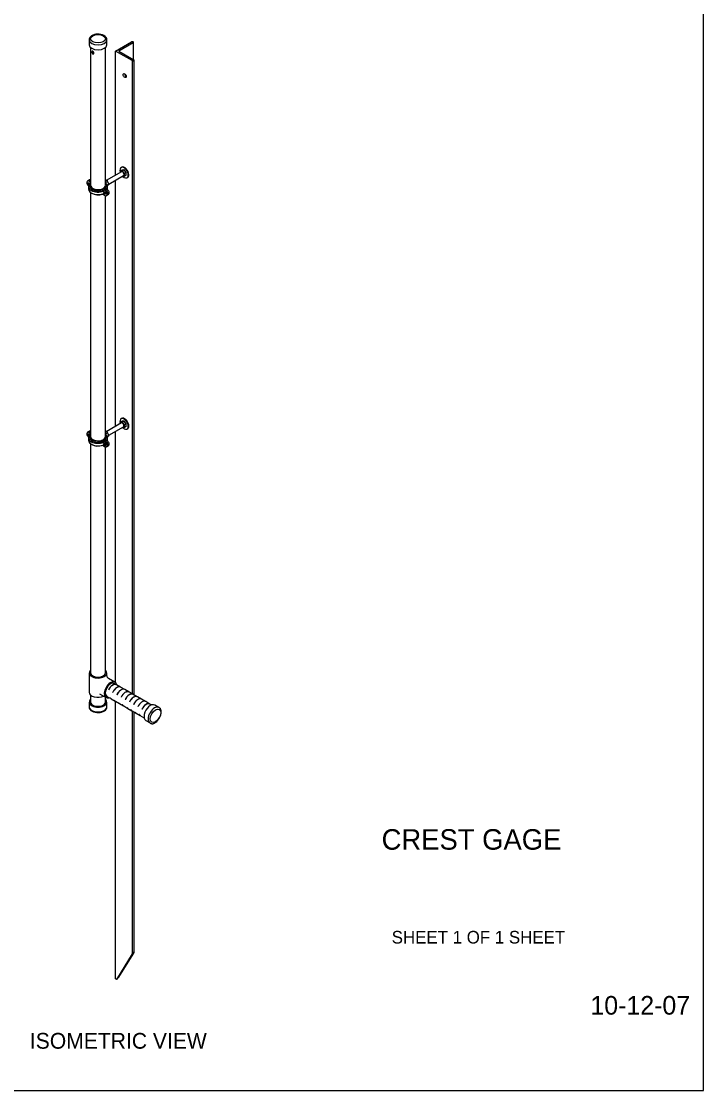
# Model space of a CAD drawing. Extents: x 99862 to 103151, y 100000 to 102076.
# Drawn here: x 102286 to 103151, y 100000 to 101354 of the extents above; entities that cross this region are included whole.
import ezdxf

# ---------------------------------------------------------------- set-up
doc = ezdxf.new("R2010")
doc.units = 0
for name, color, linetype in [('Level 1', 7, 'Continuous'), ('Level 10', 7, 'Continuous'), ('Level 13', 7, 'Continuous'), ('Level 15', 7, 'Continuous'), ('Level 20', 7, 'Continuous'), ('Level 27', 7, 'Continuous'), ('Level 3', 7, 'Continuous'), ('Level 4', 7, 'Continuous'), ('Level 5', 7, 'Continuous'), ('Level 62', 7, 'Continuous'), ('Level 7', 7, 'Continuous'), ('Level 8', 7, 'Continuous')]:
    doc.layers.add(name, color=color, linetype=linetype)

msp = doc.modelspace()

# ---------------------------------------------------------------- linework, layer by layer
at = {"layer": 'Level 1'}
msp.add_lwpolyline([(99862, 99999.5), (103151, 99999.5), (103151, 102075.5), (99862, 102075.5)], close=True, dxfattribs=at)
at = {"layer": 'Level 10'}
for p, q in [((102406.1, 100513.9), (102403.5, 100515.5)), ((102411.4, 100510.9), (102406.3, 100513.9)), ((102416.8, 100507.8), (102411.6, 100510.8)), ((102394.3, 100499.1), (102399.4, 100496.2)), ((102396.4, 100507.5), (102396.2, 100507.3)), ((102396.3, 100507.3), (102396.2, 100507.3)), ((102401.7, 100504.4), (102401.5, 100504.3)), ((102401.6, 100504.2), (102401.5, 100504.3)), ((102407, 100501.4), (102406.8, 100501.2)), ((102406.9, 100501.1), (102406.8, 100501.2)), ((102412.3, 100498.3), (102412.1, 100498.2)), ((102412.2, 100498.1), (102412.1, 100498.2)), ((102422.1, 100504.7), (102416.9, 100507.7)), ((102427.4, 100501.7), (102422.2, 100504.7)), ((102432.7, 100498.6), (102427.5, 100501.6)), ((102438, 100495.6), (102432.8, 100498.5)), ((102399.6, 100496.1), (102404.7, 100493.1)), ((102404.9, 100493), (102410, 100490)), ((102410.2, 100490), (102415.3, 100487)), ((102415.5, 100486.9), (102420.6, 100483.9)), ((102417.6, 100495.2), (102417.4, 100495.1)), ((102417.5, 100495), (102417.4, 100495.1)), ((102420.8, 100483.8), (102425.9, 100480.8)), ((102422.9, 100492.2), (102422.7, 100492)), ((102422.8, 100492), (102422.7, 100492)), ((102428.2, 100489.1), (102428, 100489)), ((102428.1, 100488.9), (102428, 100489)), ((102433.5, 100486), (102433.3, 100485.9)), ((102433.4, 100485.8), (102433.3, 100485.9)), ((102443.3, 100492.5), (102438.1, 100495.5)), ((102448.6, 100489.4), (102443.4, 100492.4)), ((102450.8, 100488.2), (102448.7, 100489.4)), ((102426.1, 100480.8), (102431.2, 100477.8)), ((102431.4, 100477.7), (102436.5, 100474.7)), ((102436.7, 100474.6), (102441.4, 100471.9)), ((102438.8, 100483), (102438.6, 100482.8)), ((102438.7, 100482.8), (102438.6, 100482.8))]:
    msp.add_line(p, q, dxfattribs=at)
for centre, major_axis, start_param, end_param in [((102401.5, 100505.8), (4.69, 8.12), 6.269043, 7.995879), ((102401.6, 100505.7), (-4.69, -8.12), 3.141562, 4.854286), ((102406.8, 100502.7), (4.69, 8.12), 6.269043, 7.995879), ((102406.9, 100502.7), (-4.69, -8.12), 3.141593, 4.854286), ((102398.9, 100507.3), (-4.69, -8.12), 6.269043, 6.283192), ((102404.1, 100504.3), (4.69, 8.12), 2.824492, 3.155735), ((102404.2, 100504.2), (-4.69, -8.12), 5.966084, 6.283185), ((102412.1, 100499.7), (4.69, 8.12), 6.269043, 7.995879), ((102412.2, 100499.6), (-4.69, -8.12), 3.141564, 4.854286), ((102417.4, 100496.6), (4.69, 8.12), 6.269043, 7.995879), ((102417.5, 100496.5), (-4.69, -8.12), 3.141555, 4.854286), ((102422.7, 100493.6), (4.69, 8.12), 6.269043, 7.995879), ((102422.8, 100493.5), (-4.69, -8.12), 3.141567, 4.854286), ((102428, 100490.5), (4.69, 8.12), 6.269043, 7.995879), ((102428.1, 100490.4), (-4.69, -8.12), 3.141593, 4.854286), ((102409.4, 100501.2), (4.69, 8.12), 2.824492, 3.155735), ((102409.5, 100501.1), (-4.69, -8.12), 5.966084, 6.283185), ((102414.7, 100498.2), (4.69, 8.12), 2.824492, 3.155735), ((102414.8, 100498.1), (-4.69, -8.12), 5.966084, 6.283185), ((102420, 100495.1), (4.69, 8.12), 2.824492, 3.155735), ((102420.2, 100495), (-4.69, -8.12), 5.966084, 6.283203), ((102425.3, 100492), (4.69, 8.12), 2.824492, 3.155735), ((102425.5, 100492), (-4.69, -8.12), 5.966084, 6.283185), ((102433.3, 100487.4), (4.69, 8.12), 6.269043, 7.995879), ((102433.4, 100487.4), (-4.69, -8.12), 3.141562, 4.854286), ((102438.6, 100484.4), (4.69, 8.12), 6.269043, 7.995879), ((102438.7, 100484.3), (-4.69, -8.12), 3.141559, 4.854286), ((102443.9, 100481.3), (4.69, 8.12), 6.269043, 7.995879), ((102444, 100481.2), (-4.69, -8.12), 3.141565, 4.854286), ((102430.6, 100489), (4.69, 8.12), 2.824492, 3.155735), ((102430.8, 100488.9), (-4.69, -8.12), 5.966084, 6.283185), ((102435.9, 100485.9), (4.69, 8.12), 2.824492, 3.155735), ((102436.1, 100485.8), (-4.69, -8.12), 5.966084, 6.283185), ((102441.2, 100482.8), (4.69, 8.12), 2.824492, 3.155735), ((102441.4, 100482.8), (-4.69, -8.12), 5.966084, 6.283185), ((102446.5, 100479.8), (4.69, 8.12), 2.824492, 3.035327), ((102446.7, 100479.7), (4.69, 8.12), 2.824492, 3.000447), ((102446.7, 100479.7), (-4.69, -8.12), 6.141288, 6.14204)]:
    msp.add_ellipse(centre, major_axis=major_axis, ratio=0.57735, start_param=start_param, end_param=end_param, dxfattribs=at)
for points in [[(102398.3, 100497.3), (102398.3, 100497.4), (102398.2, 100497.4), (102398.2, 100497.4)], [(102403.6, 100494.3), (102403.6, 100494.3), (102403.5, 100494.3), (102403.5, 100494.3)], [(102408.9, 100491.2), (102408.9, 100491.2), (102408.8, 100491.3), (102408.8, 100491.3)], [(102414.2, 100488.1), (102414.2, 100488.2), (102414.1, 100488.2), (102414.1, 100488.2)], [(102419.5, 100485.1), (102419.5, 100485.1), (102419.5, 100485.1), (102419.4, 100485.2)], [(102424.8, 100482), (102424.8, 100482), (102424.8, 100482.1), (102424.7, 100482.1)], [(102430.1, 100479), (102430.1, 100479), (102430.1, 100479), (102430, 100479)], [(102435.5, 100475.9), (102435.4, 100475.9), (102435.4, 100475.9), (102435.3, 100476)], [(102440.8, 100472.8), (102440.7, 100472.9), (102440.7, 100472.9), (102440.6, 100472.9)]]:
    msp.add_open_spline(points, degree=2, dxfattribs=at)
at = {"layer": 'Level 13'}
for p, q in [((102370.7, 101152.8), (102369.4, 101152.1)), ((102370.4, 101150), (102371.3, 101150)), ((102372.1, 101153.6), (102370.7, 101152.8)), ((102373.5, 101150.6), (102371.3, 101151.9)), ((102371.3, 101150), (102372.2, 101149)), ((102372.2, 101149), (102372.2, 101148.6)), ((102373.5, 101152.1), (102372.6, 101152.7)), ((102373, 101149.4), (102373.4, 101149.1)), ((102395, 101152), (102392.3, 101153.6)), ((102392.3, 101150.4), (102395, 101152)), ((102393.5, 101148.7), (102392.8, 101148.3)), ((102394.7, 101147), (102396.5, 101148)), ((102396.5, 101148), (102395, 101152)), ((102395, 101145.9), (102396.5, 101148)), ((102370.7, 101145.2), (102370.7, 101142.1)), ((102372.6, 101146.7), (102372.6, 101145.2)), ((102388.7, 101141.8), (102388.7, 101140.3)), ((102391.7, 101140.1), (102388.7, 101141.8)), ((102390.1, 101139.5), (102388.7, 101140.3)), ((102388.7, 101136), (102388.7, 101135.7)), ((102388.7, 101135.7), (102391.7, 101134)), ((102393.1, 101140.8), (102389.5, 101142.9)), ((102390.1, 101139.5), (102390.1, 101136.5)), ((102390.8, 101138.2), (102391.7, 101138.2)), ((102394.4, 101141.6), (102391.4, 101143.4)), ((102391.7, 101138.2), (102392.6, 101137.2)), ((102392.6, 101137.2), (102392.6, 101136.5)), ((102392.6, 101136.5), (102392.6, 101135.9)), ((102393.2, 101145.2), (102393.2, 101146.7)), ((102393.6, 101133.8), (102394.9, 101134.5)), ((102394.9, 101134.5), (102396.3, 101135.3)), ((102395, 101145.9), (102395, 101145.9)), ((102395.1, 101142.1), (102395.1, 101145.2)), ((102370.8, 100834.4), (102369.4, 100833.7)), ((102370.4, 100831.6), (102371.3, 100831.6)), ((102370.7, 100826.8), (102370.7, 100823.7)), ((102372.1, 100835.2), (102370.8, 100834.4)), ((102373.5, 100832.2), (102371.3, 100833.5)), ((102371.3, 100831.6), (102372.2, 100830.6)), ((102372.2, 100830.6), (102372.2, 100830.2)), ((102373.5, 100833.7), (102372.6, 100834.2)), ((102372.6, 100828.3), (102372.6, 100826.8)), ((102373.1, 100830.9), (102373.4, 100830.7)), ((102388.7, 100823.4), (102388.7, 100821.9)), ((102391.8, 100821.7), (102388.7, 100823.4)), ((102393.1, 100822.4), (102389.5, 100824.5)), ((102394.4, 100823.2), (102391.4, 100824.9)), ((102395, 100833.6), (102392.3, 100835.2)), ((102392.3, 100832), (102395, 100833.6)), ((102393.5, 100830.3), (102392.8, 100829.9)), ((102393.2, 100826.8), (102393.2, 100828.3)), ((102394.7, 100828.5), (102396.6, 100829.6)), ((102396.6, 100829.6), (102395, 100833.6)), ((102395, 100827.4), (102396.6, 100829.6)), ((102395, 100827.4), (102395, 100827.4)), ((102395.1, 100823.7), (102395.1, 100826.8)), ((102390.1, 100821.1), (102388.7, 100821.9)), ((102388.7, 100817.6), (102388.7, 100817.3)), ((102388.7, 100817.3), (102391.8, 100815.5)), ((102390.1, 100821.1), (102390.1, 100818)), ((102390.8, 100819.8), (102391.8, 100819.8)), ((102391.8, 100819.8), (102392.7, 100818.8)), ((102392.7, 100818.8), (102392.7, 100818.1)), ((102392.7, 100818.1), (102392.7, 100817.5)), ((102393.6, 100815.4), (102395, 100816.1)), ((102395, 100816.1), (102396.3, 100816.9))]:
    msp.add_line(p, q, dxfattribs=at)
for centre, major_axis, start_param, end_param in [((102371.3, 101148.8), (1.87, -3.25), 2.356194, 5.30587), ((102382.9, 101145.2), (-12.2, 0), 5.652247, 8.48492), ((102372.6, 101149.6), (1.87, -3.25), 2.356194, 3.14164), ((102382.9, 101146.7), (10.3, 0), 2.705832, 5.314952), ((102373.9, 101150.4), (1.87, -3.25), 2.515652, 3.141596), ((102382.9, 101146.7), (10.3, 0), 5.680622, 6.706742), ((102382.9, 101145.2), (-12.2, 0), 2.668961, 3.657263), ((102382.9, 101142.1), (-12.2, 0), 6.283185, 8.48492), ((102382.9, 101145.2), (10.3, 0), 3.141591, 5.314952), ((102382.9, 101146.7), (9.37, 0), 3.066795, 6.282088), ((102382.9, 101140.6), (10.3, 0), 3.839772, 5.314952), ((102391.7, 101137), (1.87, -3.25), 5.497787, 8.63938), ((102382.9, 101145.2), (10.3, 0), 5.869956, 6.283185), ((102393.1, 101137.8), (1.87, -3.25), 6.283185, 8.63938), ((102394.4, 101138.6), (1.87, -3.25), 0, 2.356194), ((102382.9, 101142.1), (-12.2, 0), 3.010441, 3.141593), ((102371.3, 100830.4), (1.87, -3.25), 2.356194, 5.30587), ((102382.9, 100826.8), (-12.2, 0), 5.652247, 8.48492), ((102382.9, 100823.7), (-12.2, 0), 6.283185, 8.48492), ((102372.6, 100831.2), (1.87, -3.25), 2.356194, 3.141593), ((102382.9, 100828.3), (10.3, 0), 2.710769, 5.314952), ((102374, 100831.9), (1.87, -3.25), 2.523823, 3.141593), ((102382.9, 100826.8), (10.3, 0), 3.141593, 5.314952), ((102382.9, 100828.3), (9.37, 0), 3.10947, 3.29473), ((102382.9, 100828.3), (10.3, 0), 5.680622, 6.711758), ((102382.9, 100826.8), (10.3, 0), 5.869956, 6.283185), ((102393.1, 100819.4), (1.87, -3.25), 6.283151, 8.63938), ((102382.9, 100826.8), (-12.2, 0), 2.668961, 3.657263), ((102394.4, 100820.1), (1.87, -3.25), 0, 2.356194), ((102382.9, 100823.7), (-12.2, 0), 3.010441, 3.141593), ((102382.9, 100822.2), (10.3, 0), 3.839772, 5.314952), ((102391.8, 100818.6), (1.87, -3.25), 5.497787, 8.63938)]:
    msp.add_ellipse(centre, major_axis=major_axis, ratio=0.57735, start_param=start_param, end_param=end_param, dxfattribs=at)
at = {"layer": 'Level 27'}
for p, q in [((102426.2, 101304.7), (102426.2, 100502.4)), ((102426.2, 100480.7), (102426.2, 100172.7))]:
    msp.add_line(p, q, dxfattribs=at)
at = {"layer": 'Level 3'}
for p, q in [((102373.5, 101321.3), (102373.5, 101146.3)), ((102392.3, 101146.7), (102392.3, 101321.3)), ((102412.5, 101164), (102393.3, 101153)), ((102412.3, 101169.3), (102412.9, 101169.7)), ((102369.7, 101149.6), (102370.4, 101150)), ((102370.6, 101149.6), (102371.3, 101150)), ((102371.5, 101148.6), (102372.2, 101149)), ((102396.5, 101148.3), (102415.3, 101159.1)), ((102419.8, 101156.3), (102420.4, 101156.7)), ((102373.5, 101137.6), (102373.5, 100828.1)), ((102390.2, 101137.8), (102390.8, 101138.2)), ((102391.1, 101137.8), (102391.7, 101138.2)), ((102392.6, 101137.2), (102392, 101136.8)), ((102392, 101135.5), (102392.6, 101135.9)), ((102392.3, 100828.3), (102392.3, 101133.7)), ((102412.3, 100850.9), (102412.9, 100851.3)), ((102412.5, 100845.6), (102393.3, 100834.5)), ((102396.5, 100829.9), (102415.3, 100840.7)), ((102419.8, 100837.9), (102420.4, 100838.3)), ((102369.7, 100831.2), (102370.4, 100831.6)), ((102370.7, 100831.2), (102371.3, 100831.6)), ((102371.5, 100830.2), (102372.2, 100830.6)), ((102373.5, 100819.2), (102373.5, 100528.8)), ((102390.8, 100819.8), (102390.2, 100819.4)), ((102391.8, 100819.8), (102391.1, 100819.4)), ((102392.7, 100818.8), (102392, 100818.4)), ((102392, 100817.1), (102392.7, 100817.5)), ((102392.3, 100528.8), (102392.3, 100815.3)), ((102373.5, 100500.7), (102373.5, 100491.9)), ((102392.3, 100491.9), (102392.3, 100498.1))]:
    msp.add_line(p, q, dxfattribs=at)
for points in [[(102369.7, 101149.6), (102370.6, 101149.6), (102371.5, 101148.6), (102371.5, 101147.9), (102371.5, 101147.8)], [(102371.2, 101147.3), (102370.6, 101147.3), (102369.7, 101148.3), (102369.7, 101149), (102369.7, 101149.6)], [(102369.7, 100831.2), (102370.7, 100831.2), (102371.5, 100830.2), (102371.5, 100829.5), (102371.5, 100829.4)], [(102371.3, 100828.9), (102370.7, 100828.8), (102369.7, 100829.9), (102369.7, 100830.6), (102369.7, 100831.2)]]:
    msp.add_lwpolyline(points, dxfattribs=at)
for points in [[(102390.2, 101137.8), (102391.1, 101137.8), (102392, 101136.8), (102392, 101136.1), (102392, 101135.5), (102391.1, 101135.5), (102390.2, 101136.5), (102390.2, 101137.2)], [(102390.2, 100819.4), (102391.1, 100819.4), (102392, 100818.4), (102392, 100817.7), (102392, 100817.1), (102391.1, 100817), (102390.2, 100818.1), (102390.2, 100818.7)]]:
    msp.add_lwpolyline(points, close=True, dxfattribs=at)
for centre, major_axis, start_param, end_param in [((102416, 101162.8), (3.75, -6.5), 3.053089, 4.328234), ((102416, 101162.8), (3.75, -6.5), 5.157156, 9.336274), ((102416.7, 101163.2), (3.75, -6.5), 0.785398, 3.141593), ((102416.7, 101163.2), (3.75, -6.5), 6.283159, 7.068583), ((102416, 100844.4), (3.75, -6.5), 3.053089, 4.328234), ((102416, 100844.4), (3.75, -6.5), 5.157156, 9.336274), ((102416.7, 100844.8), (3.75, -6.5), 6.283185, 9.42482), ((102382.9, 100828.3), (-9.37, 0), 0.149717, 3.141593)]:
    msp.add_ellipse(centre, major_axis=major_axis, ratio=0.57735, start_param=start_param, end_param=end_param, dxfattribs=at)
for points in [[(102376.3, 101316.4), (102376.4, 101316.4), (102376.6, 101316.2), (102376.7, 101316.1), (102376.9, 101316), (102377, 101315.8), (102377.1, 101315.7), (102377.3, 101315.5), (102377.4, 101315.3), (102377.5, 101315.1), (102377.6, 101315), (102377.6, 101314.8), (102377.7, 101314.6), (102377.7, 101314.4), (102377.7, 101314.2), (102377.7, 101314.1), (102377.7, 101313.9), (102377.7, 101313.8), (102377.6, 101313.6), (102377.5, 101313.5), (102377.4, 101313.4), (102377.3, 101313.3), (102377.2, 101313.3), (102377, 101313.2), (102376.9, 101313.2), (102376.7, 101313.2), (102376.6, 101313.2), (102376.4, 101313.3), (102376.3, 101313.4), (102376.1, 101313.4), (102376, 101313.6), (102375.9, 101313.7), (102375.7, 101313.8), (102375.6, 101314), (102375.5, 101314.2), (102375.4, 101314.4), (102375.3, 101314.6), (102375.2, 101314.8), (102375.2, 101315), (102375.1, 101315.2), (102375.1, 101315.3), (102375.1, 101315.5), (102375.1, 101315.7), (102375.1, 101315.9), (102375.1, 101316), (102375.1, 101316.2), (102375.2, 101316.3), (102375.2, 101316.4), (102375.3, 101316.5), (102375.4, 101316.6), (102375.5, 101316.6), (102375.6, 101316.6), (102375.7, 101316.6), (102375.8, 101316.6), (102375.9, 101316.6), (102376, 101316.6), (102376.2, 101316.5), (102376.3, 101316.4)], [(102376.4, 101316.3), (102376.5, 101316.2), (102376.5, 101316), (102376.5, 101315.8), (102376.6, 101315.6), (102376.6, 101315.4), (102376.7, 101315.2), (102376.8, 101315), (102376.9, 101314.8), (102377, 101314.7), (102377.1, 101314.5), (102377.3, 101314.4), (102377.4, 101314.3), (102377.5, 101314.2), (102377.6, 101314.1), (102377.7, 101314.1)]]:
    msp.add_open_spline(points, degree=3, dxfattribs=at)
at = {"layer": 'Level 4'}
for p, q in [((102371.6, 100528.8), (102371.6, 100504.3)), ((102394.1, 100525.2), (102394.1, 100528.8)), ((102404.4, 100517.1), (102396, 100521.9)), ((102403.5, 100515.5), (102403.5, 100515.5)), ((102384.8, 100502.5), (102393.2, 100497.6))]:
    msp.add_line(p, q, dxfattribs=at)
msp.add_arc((102397.9, 100525.2), 3.75, 180, 240, dxfattribs=at)
for centre, major_axis, start_param, end_param in [((102382.9, 100528.8), (11.2, 0), 2.555907, 5.497787), ((102382.9, 100528.8), (9.37, 0), 3.141593, 6.283146), ((102382.9, 100528.8), (11.2, 0), 5.497787, 6.868871), ((102382.9, 100528.8), (9.37, 0), 6.283146, 6.283225), ((102398.8, 100507.3), (5.62, 9.74), 5.6975, 10.010464), ((102398.8, 100507.3), (-4.69, -8.12), 3.14156, 6.297328), ((102382.9, 100504.3), (11.2, 0), 3.141593, 5.416818)]:
    msp.add_ellipse(centre, major_axis=major_axis, ratio=0.57735, start_param=start_param, end_param=end_param, dxfattribs=at)
at = {"layer": 'Level 5'}
for p, q in [((102371.6, 101331), (102371.6, 101324.9)), ((102394.1, 101324.9), (102394.1, 101331)), ((102371.6, 100491.9), (102371.6, 100485.8)), ((102394.1, 100485.8), (102394.1, 100491.9)), ((102460.1, 100484.9), (102454.8, 100488)), ((102443.6, 100468.5), (102448.9, 100465.4))]:
    msp.add_line(p, q, dxfattribs=at)
for centre, major_axis in [((102382.9, 101332.5), (9.37, 0)), ((102455.8, 100474.4), (-4.69, -8.12))]:
    msp.add_ellipse(centre, major_axis=major_axis, ratio=0.57735, dxfattribs=at)
for centre, major_axis, start_param, end_param in [((102382.9, 101331), (11.2, 0), 3.141593, 6.283185), ((102382.9, 101324.9), (11.2, 0), 3.141593, 6.283185), ((102382.9, 100491.9), (-11.2, 0), 5.6975, 10.010464), ((102382.9, 100485.8), (-11.2, 0), 0, 3.141593), ((102382.9, 100491.9), (-9.37, 0), 6.283137, 9.424778), ((102449.2, 100478.3), (-5.62, -9.74), 3.141562, 6.283185), ((102454.5, 100475.2), (-5.62, -9.74), 3.141593, 6.283185)]:
    msp.add_ellipse(centre, major_axis=major_axis, ratio=0.57735, start_param=start_param, end_param=end_param, dxfattribs=at)
for points, degree in [([(102394.1, 101331), (102394.2, 101333.3), (102391.2, 101337.1), (102382.3, 101339), (102374.1, 101336.7), (102371.6, 101333), (102371.6, 101331)], 3), ([(102371.6, 100485.8), (102371.6, 100483.5), (102374.6, 100479.7), (102383.5, 100477.8), (102391.7, 100480.1), (102394.2, 100483.8), (102394.1, 100485.8)], 3), ([(102455.4, 100465.9), (102458.1, 100467.5), (102463.8, 100474.7), (102463.4, 100483.1), (102460.1, 100484.9)], 3), ([(102448.9, 100465.4), (102450.8, 100464.3), (102453.3, 100464.6), (102455.4, 100465.9)], 2)]:
    msp.add_open_spline(points, degree=degree, dxfattribs=at)
at = {"layer": 'Level 7'}
for p, q in [((102413.4, 101166.1), (102411.2, 101164.9)), ((102413.9, 101165.1), (102411.2, 101164.9)), ((102411.2, 101164.9), (102411.2, 101163.3)), ((102416, 101166.4), (102413.4, 101166.1)), ((102416, 101166.4), (102413.9, 101165.1)), ((102416.5, 101161.8), (102413.9, 101165.1)), ((102418.7, 101163.1), (102416, 101166.4)), ((102418.7, 101163.1), (102416.5, 101161.8)), ((102416.5, 101158.3), (102416.5, 101161.8)), ((102418.7, 101159.5), (102418.7, 101163.1)), ((102413.7, 101158.2), (102413.9, 101158)), ((102413.9, 101158), (102416.5, 101158.3)), ((102415.3, 101159.1), (102415.3, 101159.1)), ((102418.7, 101159.5), (102416.5, 101158.3)), ((102413.4, 100847.7), (102411.2, 100846.4)), ((102413.9, 100846.7), (102411.2, 100846.4)), ((102411.2, 100846.4), (102411.2, 100844.9)), ((102416, 100847.9), (102413.4, 100847.7)), ((102413.7, 100839.8), (102413.9, 100839.6)), ((102416, 100847.9), (102413.9, 100846.7)), ((102416.5, 100843.4), (102413.9, 100846.7)), ((102413.9, 100839.6), (102416.5, 100839.8)), ((102415.3, 100840.7), (102415.3, 100840.7)), ((102418.7, 100844.6), (102416, 100847.9)), ((102418.7, 100844.6), (102416.5, 100843.4)), ((102416.5, 100839.8), (102416.5, 100843.4)), ((102418.7, 100841.1), (102416.5, 100839.8)), ((102418.7, 100841.1), (102418.7, 100844.6))]:
    msp.add_line(p, q, dxfattribs=at)
for centre, start_param, end_param in [((102413.9, 101161.6), 3.141551, 6.283103), ((102413.9, 101161.6), 6.283103, 6.283268), ((102413.9, 100843.1), 3.141551, 6.283185)]:
    msp.add_ellipse(centre, major_axis=(-1.41, 2.44), ratio=0.57735, start_param=start_param, end_param=end_param, dxfattribs=at)
at = {"layer": 'Level 8'}
for p, q in [((102405.2, 101316.8), (102425.4, 101328.5)), ((102427.4, 101327.3), (102409.2, 101316.8)), ((102427.8, 101306), (102427.8, 101327.9)), ((102405.2, 101159.8), (102405.2, 101316.8)), ((102426.2, 101304.7), (102405.2, 101316.8)), ((102409.2, 101316.8), (102428.2, 101305.8)), ((102428.6, 100501), (102428.6, 101305.3)), ((102415.3, 101288.1), (102415.3, 101288.1)), ((102418.1, 101283.2), (102418.1, 101283.2)), ((102405.2, 100841.4), (102405.2, 101153.3)), ((102405.2, 100516.5), (102405.2, 100834.9)), ((102405.2, 100141), (102405.2, 100492.8)), ((102428.6, 100174.8), (102428.6, 100479.3)), ((102426.2, 100172.7), (102406.2, 100140.5)), ((102409.2, 100143.3), (102428.2, 100173.8)), ((102406.2, 100140.5), (102405.2, 100141)), ((102406.2, 100140.5), (102407.2, 100141)), ((102407.2, 100141), (102409.2, 100143.3))]:
    msp.add_line(p, q, dxfattribs=at)
for centre, major_axis, ratio, start_param, end_param in [((102426.4, 101327.9), (1.41, 0), 0.57735, 5.497787, 8.63938), ((102427.2, 101305.3), (-1.41, 0), 0.57735, 0.785398, 3.926991), ((102418.7, 101286.8), (1.41, -2.44), 0.57735, 3.926991, 5.497787), ((102427.2, 100173.3), (1.36, 1.68), 0.22021, 5.231631, 8.373223)]:
    msp.add_ellipse(centre, major_axis=major_axis, ratio=ratio, start_param=start_param, end_param=end_param, dxfattribs=at)
msp.add_ellipse((102416.7, 101285.7), major_axis=(-1.41, 2.44), ratio=0.57735, dxfattribs=at)

# ---------------------------------------------------------------- texts
at = {"layer": 'Level 15'}
msp.add_text('10-12-07', height=23.62, dxfattribs=at).set_placement((103007.4, 100095.8))
at = {"layer": 'Level 20'}
msp.add_text('ISOMETRIC VIEW', height=20, dxfattribs=at).set_placement((102296.5, 100052.6))
at = {"layer": 'Level 62'}
for s, height, p in [('CREST GAGE', 26, (102742.6, 100304.8)), ('SHEET 1 OF 1 SHEET', 16, (102755.4, 100185.9))]:
    msp.add_text(s, height=height, dxfattribs=at).set_placement(p)

doc.saveas('drawing.dxf')
